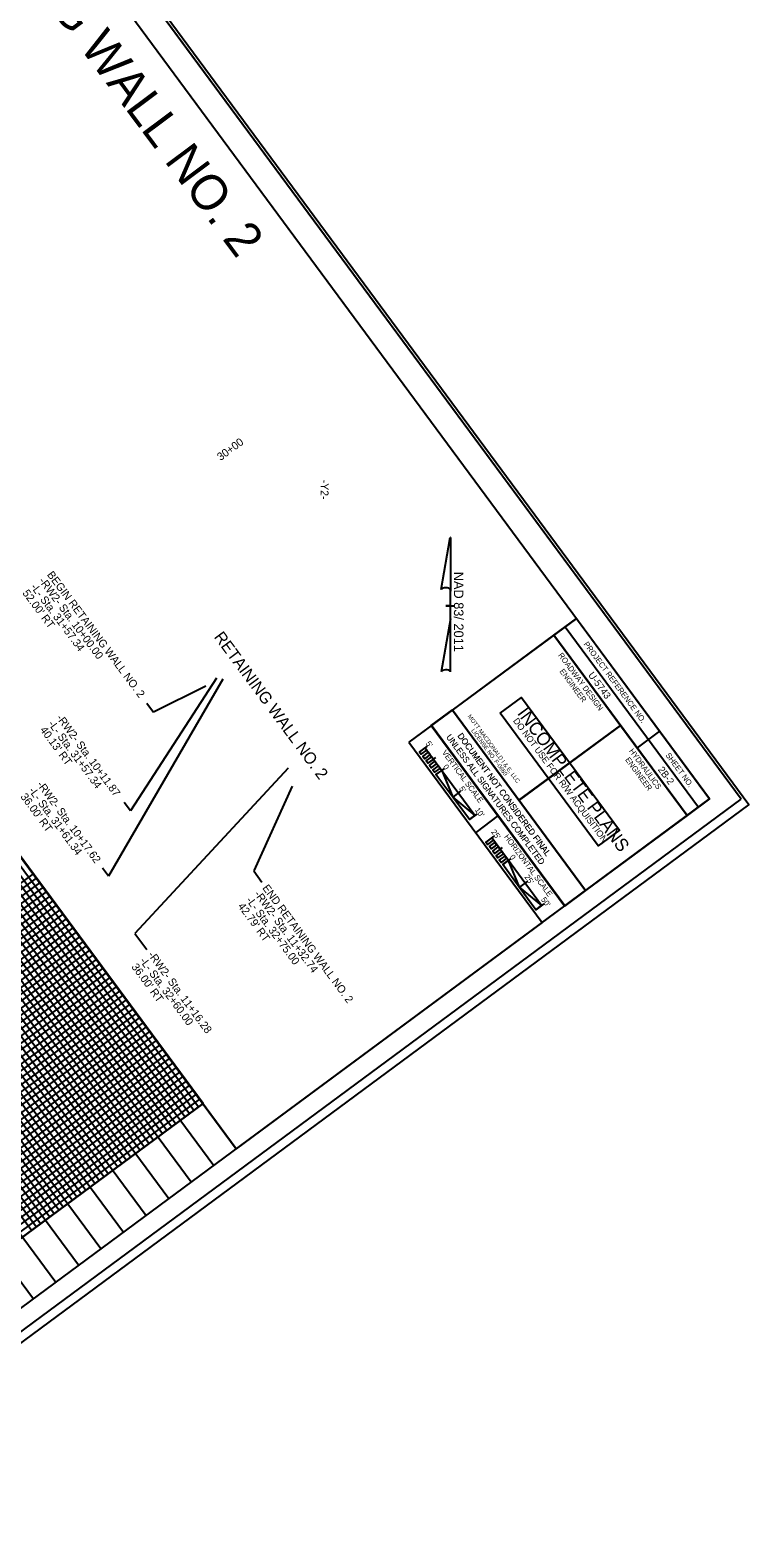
# Model space of a CAD drawing. Extents: x 1762445 to 1764340, y 710860 to 712881.
# Drawn here: x 1763699 to 1764340, y 710860 to 712205 of the extents above; entities that cross this region are included whole.
import ezdxf

# ---------------------------------------------------------------- set-up
doc = ezdxf.new("R2010")
doc.units = 0
for name, color, linetype in [('Default', 7, 'Continuous'), ('Exist Roads EOP', 7, 'Continuous'), ('Old_Level_2', 7, 'Continuous'), ('Old_Level_3', 7, 'Continuous'), ('Old_Level_38', 7, 'Continuous'), ('Old_Level_40', 7, 'Continuous'), ('Old_Level_42', 7, 'Continuous'), ('Old_Level_5', 7, 'Continuous'), ('Old_Level_62', 7, 'Continuous'), ('Old_Level_63', 7, 'Continuous'), ('Prop Conc 2ft 6in Curb and Gutter', 7, 'Continuous'), ('Prop Conc Curb 8in x 6in', 7, 'Continuous'), ('Prop Dimension', 7, 'Continuous'), ('Prop EOT', 7, 'Continuous'), ('Prop EOT Dash', 7, 'Continuous'), ('Prop Guardrail', 7, 'Continuous'), ('Prop Guardrail Anchor Unit CELL', 7, 'Continuous'), ('Prop Horizontal Alignment Direction Label', 7, 'Continuous'), ('Prop Lane Arrow CELL', 7, 'Continuous'), ('Prop North Arrow NAD83 for Plan Sheets CELL', 7, 'Continuous'), ('Prop Roadway Culvert', 7, 'Continuous'), ('Prop Superelevation  Arrow CELL', 7, 'Continuous'), ('Prop Superelevation Label', 7, 'Continuous'), ('Prop Terminator CELL', 7, 'Continuous')]:
    doc.layers.add(name, color=color, linetype=linetype)

msp = doc.modelspace()

# ---------------------------------------------------------------- linework, layer by layer
at = {"layer": 'Old_Level_3'}
for points in [[(1763837.4, 711235.7), (1763005.3, 712361.6), (1762997.3, 712355.6), (1763829.3, 711229.7)], [(1763845.4, 711241.6), (1763013.3, 712367.5), (1763009.3, 712364.6), (1763841.4, 711238.7)], [(1763017.4, 712370.5), (1763849.4, 711244.6)], [(1763817.3, 711220.8), (1762985.2, 712346.7), (1762977.2, 712340.8), (1763809.2, 711214.9)], [(1763825.3, 711226.8), (1762993.2, 712352.7), (1762989.2, 712349.7), (1763821.3, 711223.8)], [(1763797.2, 711206), (1762965.1, 712331.9), (1762957, 712325.9), (1763789.1, 711200)], [(1763805.2, 711211.9), (1762973.1, 712337.8), (1762969.1, 712334.8), (1763801.2, 711208.9)], [(1763785.1, 711197.1), (1762953, 712323), (1762949, 712320), (1763781.1, 711194.1)], [(1763765, 711182.2), (1762932.9, 712308.1), (1762928.9, 712305.1), (1763761, 711179.2)], [(1763777.1, 711191.1), (1762945, 712317), (1762936.9, 712311.1), (1763769, 711185.2)], [(1763744.9, 711167.3), (1762912.8, 712293.2), (1762908.8, 712290.3), (1763740.9, 711164.4)], [(1763757, 711176.3), (1762924.9, 712302.2), (1762916.8, 712296.2), (1763748.9, 711170.3)], [(1763724.8, 711152.5), (1762892.7, 712278.4), (1762888.7, 712275.4), (1763720.8, 711149.5)], [(1763736.9, 711161.4), (1762904.8, 712287.3), (1762896.7, 712281.3), (1763728.8, 711155.5)], [(1763716.7, 711146.5), (1762884.7, 712272.4), (1762876.6, 712266.5), (1763708.7, 711140.6)], [(1763704.7, 711137.6), (1762872.6, 712263.5), (1762868.6, 712260.5), (1763700.7, 711134.6)], [(1763701.9, 711452.6), (1763299.8, 711155.5), (1763305.7, 711147.4), (1763707.9, 711444.6)], [(1763710.8, 711440.6), (1763308.7, 711143.4), (1763311.7, 711139.4), (1763713.8, 711436.6)], [(1763716.8, 711432.5), (1763314.7, 711135.4), (1763320.6, 711127.3), (1763722.7, 711424.5)], [(1763725.7, 711420.5), (1763323.6, 711123.3), (1763326.5, 711119.3), (1763728.7, 711416.5)], [(1763731.6, 711412.4), (1763329.5, 711115.3), (1763335.5, 711107.2), (1763737.6, 711404.4)], [(1763740.5, 711400.4), (1763338.4, 711103.2), (1763341.4, 711099.2), (1763743.5, 711396.4)], [(1763746.5, 711392.3), (1763344.4, 711095.2), (1763350.3, 711087.1), (1763752.4, 711384.3)], [(1763755.4, 711380.3), (1763353.3, 711083.1), (1763356.3, 711079.1), (1763758.4, 711376.2)], [(1763761.3, 711372.2), (1763359.2, 711075.1), (1763365.2, 711067), (1763767.3, 711364.2)], [(1763770.3, 711360.2), (1763368.1, 711063), (1763371.1, 711059), (1763773.2, 711356.1)], [(1763776.2, 711352.1), (1763374.1, 711055), (1763380, 711046.9), (1763782.1, 711344.1)], [(1763785.1, 711340.1), (1763383, 711042.9), (1763386, 711038.9), (1763788.1, 711336)], [(1763791.1, 711332), (1763389, 711034.8), (1763394.9, 711026.8), (1763797, 711324)], [(1763800, 711320), (1763397.9, 711022.8), (1763400.8, 711018.8), (1763802.9, 711315.9)], [(1763805.9, 711311.9), (1763403.8, 711014.7), (1763409.8, 711006.7), (1763811.9, 711303.9)], [(1763814.8, 711299.8), (1763412.7, 711002.7)], [(1763412.7, 711002.7), (1763415.7, 710998.7), (1763817.8, 711295.8)], [(1763820.8, 711291.8), (1763418.7, 710994.6), (1763424.6, 710986.6), (1763826.7, 711283.8)], [(1763829.7, 711279.7), (1763427.6, 710982.6), (1763430.6, 710978.6), (1763832.7, 711275.7)], [(1763835.6, 711271.7), (1763433.5, 710974.5), (1763439.5, 710966.5), (1763841.6, 711263.7)], [(1763844.5, 711259.6), (1763442.4, 710962.5), (1763445.4, 710958.4), (1763847.5, 711255.6)], [(1763850.5, 711251.6), (1763448.4, 710954.4), (1763454.3, 710946.4)]]:
    msp.add_lwpolyline(points, dxfattribs=at)
at = {"layer": 'Old_Level_38'}
for p, q in [((1764053.5, 711566.4), (1764046.5, 711561.2)), ((1764051.5, 711564.9), (1764046.5, 711561.2)), ((1764096.1, 711504.6), (1764051.5, 711564.9)), ((1764061, 711556.4), (1764053.9, 711551.2)), ((1764068.4, 711546.3), (1764061.3, 711541.1)), ((1764083.3, 711526.2), (1764076.2, 711521)), ((1764098.1, 711506.1), (1764091.1, 711500.9)), ((1764091.1, 711500.9), (1764096.1, 711504.6)), ((1764113, 711486), (1764105.9, 711480.8)), ((1764111, 711484.5), (1764105.9, 711480.8)), ((1764155.5, 711424.2), (1764111, 711484.5)), ((1764120.4, 711475.9), (1764113.4, 711470.7)), ((1764127.8, 711465.9), (1764120.8, 711460.7)), ((1764142.7, 711445.8), (1764135.7, 711440.6)), ((1764157.6, 711425.7), (1764150.5, 711420.5)), ((1764150.5, 711420.5), (1764155.5, 711424.2))]:
    msp.add_line(p, q, dxfattribs=at)
for points in [[(1764053, 711562.9), (1764051.5, 711564.9), (1764046.5, 711561.2), (1764048, 711559.2)], [(1764054.5, 711560.9), (1764056, 711558.9), (1764051, 711555.2), (1764049.5, 711557.2)], [(1764057.5, 711556.9), (1764059, 711554.9), (1764053.9, 711551.2), (1764052.5, 711553.2)], [(1764060.4, 711552.9), (1764061.9, 711550.9), (1764056.9, 711547.1), (1764055.4, 711549.2)], [(1764063.4, 711548.8), (1764064.9, 711546.8), (1764059.9, 711543.1), (1764058.4, 711545.1)], [(1764066.4, 711544.8), (1764076.2, 711521), (1764061.3, 711541.1)], [(1764076.2, 711521), (1764096.1, 711504.6), (1764091.1, 711500.9)], [(1764112.5, 711482.5), (1764111, 711484.5), (1764105.9, 711480.8), (1764107.4, 711478.8)], [(1764113.9, 711480.5), (1764115.4, 711478.5), (1764110.4, 711474.8), (1764108.9, 711476.8)], [(1764116.9, 711476.5), (1764118.4, 711474.5), (1764113.4, 711470.7), (1764111.9, 711472.8)], [(1764119.9, 711472.4), (1764121.4, 711470.4), (1764116.3, 711466.7), (1764114.9, 711468.7)], [(1764122.9, 711468.4), (1764124.3, 711466.4), (1764119.3, 711462.7), (1764117.8, 711464.7)], [(1764125.8, 711464.4), (1764135.6, 711440.6), (1764120.8, 711460.7)], [(1764135.6, 711440.6), (1764155.5, 711424.2), (1764150.5, 711420.5)]]:
    msp.add_lwpolyline(points, close=True, dxfattribs=at)
at = {"layer": 'Old_Level_40'}
msp.add_line((1764116.8, 711504.4), (1764096.7, 711489.5), dxfattribs=at)
msp.add_lwpolyline([(1764037.2, 711570), (1764156.1, 711409.1), (1764176.2, 711423.9), (1764057.3, 711584.8)], close=True, dxfattribs=at)
at = {"layer": 'Old_Level_42'}
msp.add_line((1764176.2, 711423.9), (1764057.3, 711584.8), dxfattribs=at)
at = {"layer": 'Old_Level_5'}
msp.add_lwpolyline([(1764333.6, 711519.1), (1763332.7, 712873.4), (1762448, 712219.6), (1763448.9, 710865.3)], close=True, dxfattribs=at)
at = {"layer": 'Old_Level_62'}
msp.add_lwpolyline([(1762480.3, 712222.3), (1763461, 710895.3), (1764305.4, 711519.4), (1763324.7, 712846.3)], close=True, dxfattribs=at)
at = {"layer": 'Old_Level_63'}
msp.add_lwpolyline([(1762445.3, 712227.5), (1763455.7, 710860.4), (1764340.4, 711514.1), (1763330, 712881.3)], close=True, dxfattribs=at)
at = {"layer": 'Prop Conc 2ft 6in Curb and Gutter'}
for p, q in [((1763871.1, 711626.2), (1763769.3, 711450.3)), ((1763865.4, 711626.9), (1763788.7, 711508.8)), ((1763929.6, 711546.7), (1763792.8, 711399.3)), ((1763788.7, 711508.8), (1763783.3, 711516.1)), ((1763769.3, 711450.3), (1763763.9, 711457.6)), ((1763898.7, 711455.1), (1763906.1, 711445.1))]:
    msp.add_line(p, q, dxfattribs=at)
at = {"layer": 'Prop Dimension'}
for p, q in [((1763883.2, 711207.4), (1762991.7, 712413.7)), ((1764176.4, 711672.8), (1764295.3, 711511.9)), ((1764225.8, 711584.9), (1764135.4, 711518.1)), ((1764260.8, 711579.7), (1764240.7, 711564.8))]:
    msp.add_line(p, q, dxfattribs=at)
for points in [[(1764305.4, 711519.4), (1763413.9, 712725.7), (1762569.5, 712101.7), (1763461, 710895.3)], [(1764186.5, 711680.3), (1764305.4, 711519.4), (1764285.2, 711504.5), (1764166.3, 711665.4)], [(1764166.3, 711665.4), (1764225.8, 711584.9), (1764135.3, 711518.1), (1764075.9, 711598.5)], [(1764225.8, 711584.9), (1764285.2, 711504.5), (1764194.8, 711437.6), (1764135.3, 711518.1)]]:
    msp.add_lwpolyline(points, close=True, dxfattribs=at)
at = {"layer": 'Prop EOT'}
msp.add_line((1764268, 711538.4), (1764268, 711538.4), dxfattribs=at)
at = {"layer": 'Prop EOT Dash'}
for p, q in [((1764057, 711584.8), (1764075.9, 711598.8)), ((1764057, 711584.6), (1764075.9, 711598.5)), ((1764075.9, 711598.8), (1764194.8, 711437.9)), ((1764075.9, 711598.5), (1764194.8, 711437.7)), ((1764175.9, 711423.9), (1764057, 711584.8)), ((1764175.9, 711423.7), (1764057, 711584.6)), ((1764194.8, 711437.9), (1764175.9, 711423.9)), ((1764194.8, 711437.6), (1764175.9, 711423.7))]:
    msp.add_line(p, q, dxfattribs=at)
at = {"layer": 'Prop Horizontal Alignment Direction Label'}
for p, q in [((1763855.9, 711619.9), (1763809.2, 711596.6)), ((1763803.3, 711604.6), (1763809.2, 711596.6)), ((1763933, 711530.6), (1763898.7, 711455.1)), ((1763792.8, 711399.3), (1763803.4, 711385))]:
    msp.add_line(p, q, dxfattribs=at)
at = {"layer": 'Prop Lane Arrow CELL'}
msp.add_lwpolyline([(1764118.6, 711595.8), (1764137.5, 711609.8), (1764224.9, 711491.6), (1764206, 711477.6)], close=True, dxfattribs=at)
at = {"layer": 'Prop North Arrow NAD83 for Plan Sheets CELL'}
for p, q in [((1763883.2, 711207.4), (1762991.7, 712413.7)), ((1764186.5, 711680.3), (1764037.2, 711570)), ((1764037.2, 711570), (1764156.1, 711409.1)), ((1764156.1, 711409.1), (1763883.2, 711207.4))]:
    msp.add_line(p, q, dxfattribs=at)
msp.add_lwpolyline([(1763021.4, 712373.5), (1762619.3, 712076.3), (1763451.4, 710950.4), (1763853.5, 711247.6)], close=True, dxfattribs=at)
at = {"layer": 'Prop Roadway Culvert'}
for p, q in [((1764065.9, 711706.1), (1764074.1, 711752.5)), ((1764074.2, 711752.5), (1764074.1, 711752.5)), ((1764074.2, 711752.5), (1764074.1, 711752.5)), ((1764074.2, 711752.5), (1764074.2, 711704.7)), ((1764074.2, 711679.9), (1764074.2, 711706.1)), ((1764074.2, 711704.7), (1764074.2, 711706)), ((1764070.2, 711691.5), (1764070.1, 711691.5)), ((1764070.2, 711691.5), (1764078.2, 711691.5)), ((1764073.7, 711691.5), (1764070.2, 711691.5)), ((1764074.2, 711679.9), (1764065.8, 711632.6)), ((1764074.2, 711632.8), (1764074.2, 711679.9))]:
    msp.add_line(p, q, dxfattribs=at)
for centre, start_param, end_param in [((1764070.1, 711705.7), 0.216388, 2.908219), ((1764070.1, 711632.5), 0.201328, 3.141593)]:
    msp.add_ellipse(centre, major_axis=(4.23, -0.03), ratio=0.461098, start_param=start_param, end_param=end_param, dxfattribs=at)
at = {"layer": 'Prop Superelevation  Arrow CELL'}
for points in [[(1763843, 711177.6), (1762951.5, 712384), (1762991.7, 712413.7), (1763883.2, 711207.4)], [(1763762.5, 711118.2), (1762871, 712324.5), (1762911.2, 712354.2), (1763802.8, 711147.9)], [(1763682.1, 711058.8), (1762790.6, 712265.1), (1762830.8, 712294.8), (1763722.3, 711088.5)], [(1763675.2, 711488.8), (1763273.1, 711191.7), (1763302.8, 711151.5), (1763704.9, 711448.6)], [(1763734.6, 711408.4), (1763332.5, 711111.2), (1763362.2, 711071), (1763764.3, 711368.2)], [(1763794, 711328), (1763391.9, 711030.8), (1763421.6, 710990.6), (1763823.7, 711287.8)], [(1763853.5, 711247.6), (1763451.4, 710950.4), (1763481.1, 710910.2)]]:
    msp.add_lwpolyline(points, dxfattribs=at)
at = {"layer": 'Prop Superelevation Label'}
for points in [[(1762991.7, 712413.7), (1762971.6, 712398.8), (1763863.1, 711192.5)], [(1763822.9, 711162.8), (1762931.4, 712369.1), (1762891.1, 712339.4), (1763782.7, 711133.1)], [(1763742.4, 711103.4), (1762850.9, 712309.7), (1762810.7, 712280), (1763702.2, 711073.6)], [(1763719.7, 711428.5), (1763317.6, 711131.4), (1763347.3, 711091.1), (1763749.5, 711388.3)], [(1763779.2, 711348.1), (1763377.1, 711050.9), (1763406.8, 711010.7), (1763808.9, 711307.9)], [(1763838.6, 711267.7), (1763436.5, 710970.5)]]:
    msp.add_lwpolyline(points, dxfattribs=at)
at = {"layer": 'Prop Terminator CELL'}
msp.add_line((1764333.6, 711519.1), (1763332.7, 712873.4), dxfattribs=at)

# ---------------------------------------------------------------- texts
at = {"layer": 'Default'}
for s, height, rotation, p in [('RETAINING WALL NO. 2', 31.5, 306.7041, (1763598.8, 712383)), ('-RW2- Sta. 10+00.00', 7, 306.833, (1763706.7, 711713.7)), ('BEGIN RETAINING WALL NO. 2', 7, 306.833, (1763714, 711719.2)), ("52.00' RT", 7, 306.833, (1763692.1, 711702.8)), ('-L- Sta. 31+57.34', 7, 306.833, (1763699.4, 711708.3)), ('RETAINING WALL NO. 2', 10.5, 306.4657, (1763862.8, 711663.7)), ('-RW2- Sta. 10+11.87', 7, 306.4657, (1763722.3, 711591.6)), ("40.13' RT", 7, 306.4657, (1763707.7, 711580.8)), ('-L- Sta. 31+57.34', 7, 306.4657, (1763715, 711586.2)), ('-L- Sta. 31+61.34', 7, 306.4657, (1763697.6, 711526.8)), ('-RW2- Sta. 10+17.62', 7, 306.4657, (1763704.9, 711532.2)), ("36.00' RT", 7, 306.4657, (1763690.3, 711521.3)), ('-RW2- Sta. 11+32.74', 7, 306.4657, (1763898.8, 711434.4)), ('END RETAINING WALL NO. 2', 7, 306.4657, (1763906.1, 711439.8)), ("42.79' RT", 7, 306.4657, (1763884.2, 711423.6)), ('-L- Sta. 32+75.00', 7, 306.4657, (1763891.5, 711429)), ('-RW2- Sta. 11+16.28', 7, 306.4657, (1763804, 711380.3)), ("36.00' RT", 7, 306.4657, (1763789.3, 711369.5)), ('-L- Sta. 32+60.00', 7, 306.4657, (1763796.7, 711374.9))]:
    msp.add_text(s, height=height, rotation=rotation, dxfattribs=at).set_placement(p)
at = {"layer": 'Exist Roads EOP'}
for s, p in [('U-5743', (1764196.7, 711629.7)), ('2B-2', (1764258.9, 711545.4))]:
    msp.add_text(s, height=6.2, rotation=306.4657, dxfattribs=at).set_placement(p)
at = {"layer": 'Old_Level_2'}
for s, p in [('MOTT MACDONALD I & E, LLC', (1764089.3, 711592.9)), (' LICENSE NO. F-0669', (1764091.6, 711581.4))]:
    msp.add_text(s, height=3.75, rotation=306.4657, dxfattribs=at).set_placement(p)
at = {"layer": 'Old_Level_40'}
for s, p in [("5'", (1764051.9, 711568.6)), ('VERTICAL SCALE', (1764066.3, 711560.6)), ('0', (1764067.3, 711547.8)), ("5'", (1764081.6, 711528.4)), ("10'", (1764095.7, 711509.4)), ("25'", (1764110.2, 711489.8)), ('HORIZONTAL SCALE', (1764121.8, 711485.4)), ('0', (1764126.7, 711467.4)), ("25'", (1764139.9, 711449.6)), ("50'", (1764154.7, 711429.5))]:
    msp.add_text(s, height=5, rotation=306.4657, dxfattribs=at).set_placement(p)
at = {"layer": 'Prop Conc Curb 8in x 6in'}
for s, p in [('ENGINEER', (1764229.8, 711554.2)), ('HYDRAULICS', (1764233.2, 711562))]:
    msp.add_text(s, height=5, rotation=306.4657, dxfattribs=at).set_placement(p)
at = {"layer": 'Prop Dimension'}
for s, p in [('PROJECT REFERENCE NO.', (1764192.7, 711657.3)), ('ROADWAY DESIGN', (1764170, 711647.4)), ('ENGINEER', (1764171.2, 711633)), ('SHEET NO.', (1764265.8, 711558.2))]:
    msp.add_text(s, height=5, rotation=306.4657, dxfattribs=at).set_placement(p)
at = {"layer": 'Prop EOT Dash'}
for s, p in [('UNLESS ALL SIGNATURES COMPLETED', (1764070, 711574.5)), ('UNLESS ALL SIGNATURES COMPLETED', (1764070, 711574.3)), ('DOCUMENT NOT CONSIDERED FINAL', (1764080.1, 711575.4)), ('DOCUMENT NOT CONSIDERED FINAL', (1764080.1, 711575.7))]:
    msp.add_text(s, height=5.5, rotation=306.4657, dxfattribs=at).set_placement(p)
at = {"layer": 'Prop Guardrail'}
msp.add_text('-Y2-', height=7, rotation=268.7765, dxfattribs=at).set_placement((1763958.7, 711804.1))
at = {"layer": 'Prop Guardrail Anchor Unit CELL'}
msp.add_text('30+00', height=7, rotation=36.325, dxfattribs=at).set_placement((1763869.2, 711820.6))
at = {"layer": 'Prop Lane Arrow CELL'}
for s, height, p in [('INCOMPLETE PLANS', 11.52, (1764133.3, 711595.6)), ('DO NOT USE FOR R/W ACQUISITION', 5.76, (1764129.7, 711588.9))]:
    msp.add_text(s, height=height, rotation=306.4657, dxfattribs=at).set_placement(p)
at = {"layer": 'Prop Roadway Culvert'}
msp.add_text('NAD 83/ 2011', height=8.5, rotation=270, dxfattribs=at).set_placement((1764077.3, 711721.9))

doc.saveas('drawing.dxf')
